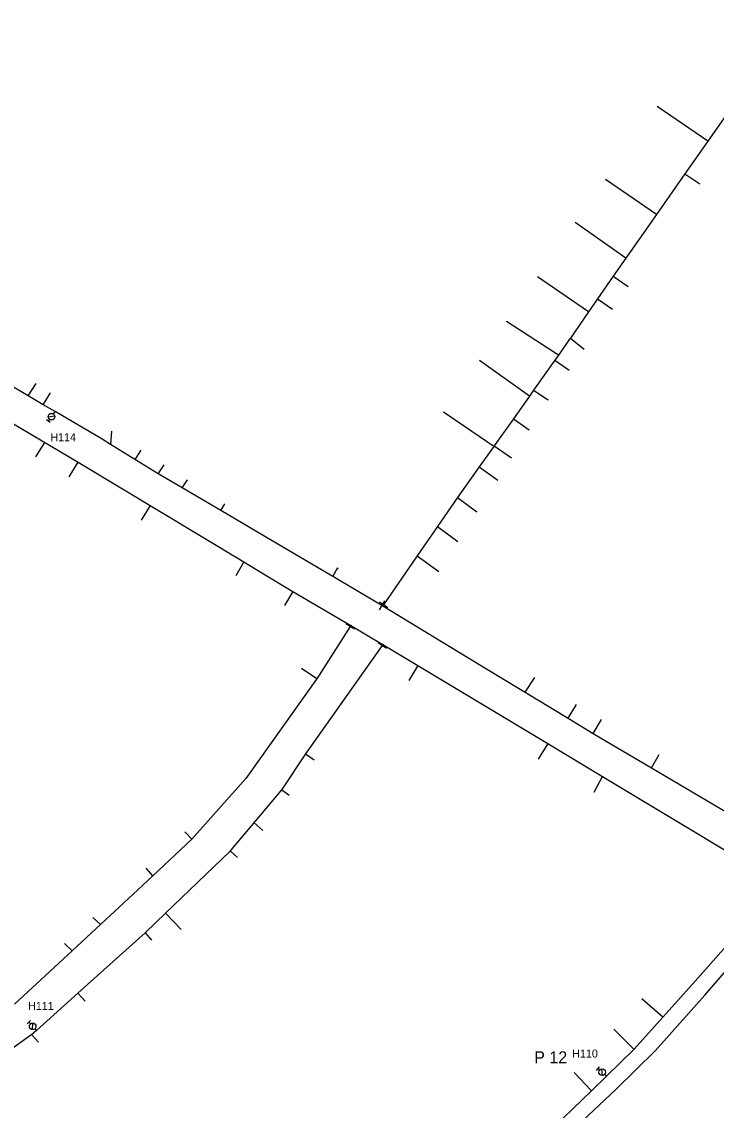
# Model space of a CAD drawing. Extents: x -548873 to -538270, y -1201997 to -1192514.
# Drawn here: x -544179.8 to -544006.3, y -1193175.5 to -1192903.5 of the extents above; entities that cross this region are included whole.
import ezdxf

# ---------------------------------------------------------------- set-up
doc = ezdxf.new("R2010")
doc.units = 0
for name, color, linetype in [('KN_HRAN_STÁTNÍ', 7, 'Continuous'), ('KN_PARC_Č', 7, 'Continuous'), ('KN_VKP_HRAN_SPORNÁ', 7, 'Continuous'), ('PK_PARC_Čv', 7, 'Continuous'), ('Vrstva 29', 7, 'Continuous')]:
    doc.layers.add(name, color=color, linetype=linetype)

# ---------------------------------------------------------------- blocks, each defined once
blk = doc.blocks.new('160')
at = {"layer": 'KN_HRAN_STÁTNÍ'}
blk.add_circle((0, 0), 0.0458, dxfattribs=at)
blk = doc.blocks.new('147')
at = {"layer": 'KN_HRAN_STÁTNÍ'}
blk.add_line((0, 1.27), (0, -1.27), dxfattribs=at)
blk = doc.blocks.new('133')
at = {"layer": 'KN_HRAN_STÁTNÍ'}
for p, q in [((0.28, 0), (0, 0)), ((0.54, 0.58), (1.7, -0.58)), ((1.94, 0), (2.52, 0)), ((2.52, 0.58), (2.52, -0.58))]:
    blk.add_line(p, q, dxfattribs=at)
blk.add_circle((1.11, 0), 0.825, dxfattribs=at)

msp = doc.modelspace()

# ---------------------------------------------------------------- linework, layer by layer
at = {"layer": 'KN_PARC_Č'}
for points in [[(-544008.387, -1192933.391), (-544021.058, -1192924.736)], [(-544021.221, -1192951.705), (-544033.938, -1192942.937)], [(-544014.091, -1192941.565), (-544010.359, -1192944.037)], [(-544028.888, -1192962.608), (-544041.542, -1192953.662)], [(-544038.189, -1192975.993), (-544050.926, -1192967.248)], [(-544032.028, -1192967.074), (-544028.307, -1192969.644)], [(-544035.944, -1192972.743), (-544032.204, -1192975.347)], [(-544045.731, -1192986.825), (-544058.699, -1192978.403)], [(-544042.741, -1192982.583), (-544039.264, -1192985.361)], [(-544052.942, -1192997.05), (-544065.489, -1192988.196)], [(-544046.636, -1192988.108), (-544043.031, -1192990.552)], [(-544178.257, -1192997.017), (-544176.267, -1192993.909)], [(-544174.516, -1192999.205), (-544172.625, -1192996.288)], [(-544051.933, -1192995.619), (-544048.311, -1192997.974)], [(-544061.89, -1193009.624), (-544074.426, -1193001.119)], [(-544056.979, -1193002.723), (-544053, -1193005.522)], [(-544157.602, -1193009.165), (-544157.322, -1193005.806)], [(-544174.129, -1193008.617), (-544176.401, -1193012.255)], [(-544151.525, -1193012.911), (-544149.983, -1193010.556)], [(-544061.78, -1193009.47), (-544057.485, -1193012.489)], [(-544165.804, -1193013.531), (-544168.08, -1193017.275)], [(-544145.737, -1193016.479), (-544144.251, -1193014.222)], [(-544065.508, -1193014.709), (-544060.898, -1193018.072)], [(-544139.736, -1193020.008), (-544138.398, -1193018.021)], [(-544147.754, -1193024.394), (-544150.019, -1193028.09)], [(-544130.135, -1193025.655), (-544129.12, -1193024.02)], [(-544070.961, -1193022.372), (-544066.089, -1193025.943)], [(-544075.98, -1193029.639), (-544070.833, -1193033.354)], [(-544081.061, -1193036.999), (-544075.641, -1193040.854)], [(-544124.358, -1193038.476), (-544126.372, -1193041.963)], [(-544102.075, -1193042.159), (-544100.864, -1193039.903)], [(-544101.026, -1193040.204), (-544100.67, -1193040.057)], [(-544112.09, -1193045.86), (-544114.147, -1193049.349)], [(-544106.12, -1193067.738), (-544109.913, -1193065.159)], [(-544080.84, -1193064.369), (-544083.103, -1193068.144)], [(-544054.015, -1193071.064), (-544051.579, -1193067.401)], [(-544043.296, -1193077.56), (-544041.178, -1193074.094)], [(-544037.046, -1193081.348), (-544034.977, -1193077.846)], [(-544048.396, -1193083.832), (-544050.746, -1193087.813)], [(-544108.927, -1193086.404), (-544106.729, -1193087.936)], [(-544022.497, -1193089.945), (-544020.577, -1193086.586)], [(-544034.732, -1193092.062), (-544036.91, -1193096.096)], [(-544114.895, -1193095.316), (-544112.994, -1193096.76)], [(-544137.317, -1193107.771), (-544139.114, -1193105.935)], [(-544121.82, -1193103.584), (-544119.612, -1193105.601)], [(-544127.781, -1193110.7), (-544125.959, -1193112.362)], [(-544147.085, -1193116.945), (-544148.783, -1193114.971)], [(-544160.187, -1193129.099), (-544162.061, -1193127.309)], [(-544143.938, -1193126.293), (-544139.971, -1193130.315)], [(-544149.001, -1193131.172), (-544147.424, -1193133.005)], [(-544167.251, -1193135.652), (-544169.156, -1193133.848)], [(-544165.873, -1193146.274), (-544164.001, -1193148.203)], [(-544019.644, -1193152.21), (-544024.849, -1193147.69)], [(-544177.353, -1193156.615), (-544175.664, -1193158.482)], [(-544026.856, -1193160.247), (-544031.866, -1193155.254)], [(-544037.454, -1193170.669), (-544041.79, -1193166.057)]]:
    msp.add_lwpolyline(points, dxfattribs=at)
at = {"layer": 'KN_VKP_HRAN_SPORNÁ'}
for points in [[(-543987.554, -1192903.537), (-543994.599, -1192913.633), (-544005.63, -1192929.441), (-544008.387, -1192933.391), (-544014.091, -1192941.565), (-544021.221, -1192951.705), (-544032.028, -1192967.074), (-544035.944, -1192972.743), (-544038.189, -1192975.993), (-544042.742, -1192982.584), (-544042.929, -1192982.851), (-544045.731, -1192986.825), (-544046.636, -1192988.108), (-544051.935, -1192995.621), (-544052.942, -1192997.05), (-544056.98, -1193002.725), (-544061.78, -1193009.47), (-544061.89, -1193009.624), (-544065.509, -1193014.71), (-544070.961, -1193022.372), (-544075.98, -1193029.639), (-544081.061, -1193036.998), (-544089.427, -1193049.251)], [(-544089.855, -1193049.347), (-544102.076, -1193042.159), (-544117.278, -1193033.217), (-544130.134, -1193025.656), (-544139.736, -1193020.008), (-544145.75, -1193016.471), (-544157.635, -1193009.145), (-544159.757, -1193007.837), (-544171.53, -1193000.951), (-544174.516, -1192999.205), (-544178.257, -1192997.017), (-544188.523, -1192991.013), (-544190.431, -1192989.897), (-544197.927, -1192985.759), (-544213.044, -1192979.259), (-544220.592, -1192976.683), (-544221.484, -1192976.379), (-544229.477, -1192973.45), (-544246.01, -1192968.29), (-544260.273, -1192963.444), (-544278.402, -1192957.285)], [(-544224.048, -1192984.419), (-544217.124, -1192986.365), (-544208.14, -1192988.89), (-544206.053, -1192990.229), (-544204.619, -1192991.15), (-544186.94, -1193001.055), (-544165.773, -1193013.549), (-544124.358, -1193038.476), (-544119.842, -1193041.194), (-544112.061, -1193045.877), (-544097.58, -1193054.366)], [(-544089.596, -1193049.499), (-544089.855, -1193049.347)], [(-544089.427, -1193049.251), (-544089.596, -1193049.499)], [(-544089.596, -1193049.499), (-544063.674, -1193065.21), (-544043.296, -1193077.56), (-544037.046, -1193081.349), (-544022.496, -1193089.945), (-544005.384, -1193100.056), (-543984.659, -1193112.301), (-543984.54, -1193112.42)], [(-544097.58, -1193054.366), (-544097.741, -1193054.619)], [(-544097.58, -1193054.366), (-544097.585, -1193054.363), (-544096.173, -1193055.203), (-544092.429, -1193057.431), (-544089.577, -1193059.128)], [(-544097.741, -1193054.619), (-544104.325, -1193064.926), (-544106.12, -1193067.737), (-544106.148, -1193067.781), (-544117.674, -1193083.955), (-544123.817, -1193092.575), (-544137.317, -1193107.771), (-544137.34, -1193107.797), (-544147.086, -1193116.946), (-544150.869, -1193120.455), (-544160.188, -1193129.1), (-544167.251, -1193135.652), (-544181.641, -1193149.001)], [(-544089.762, -1193059.399), (-544108.927, -1193086.404), (-544108.935, -1193086.416), (-544114.892, -1193095.313), (-544127.781, -1193110.7), (-544127.875, -1193110.813), (-544143.938, -1193126.293), (-544148.995, -1193131.167), (-544149.001, -1193131.172), (-544165.873, -1193146.274), (-544176.167, -1193155.556), (-544177.3, -1193156.577), (-544189.492, -1193165.255), (-544207.544, -1193177.774), (-544220.163, -1193186.006), (-544226.481, -1193190.224), (-544238.839, -1193198.475)], [(-544089.762, -1193059.399), (-544089.577, -1193059.128)], [(-544089.577, -1193059.128), (-544080.838, -1193064.37), (-544048.376, -1193083.844), (-544034.709, -1193092.076), (-544000.466, -1193112.661), (-543990.613, -1193118.584), (-543990.374, -1193118.783)], [(-544345.745, -1193444.61), (-544343.348, -1193443.882), (-544324.303, -1193438.096), (-544308.937, -1193423.077), (-544301.353, -1193415.664), (-544300.262, -1193414.734), (-544299.949, -1193414.468), (-544256.263, -1193375.958), (-544244.022, -1193365.058), (-544211.153, -1193335.791), (-544164.9, -1193294.332), (-544162.049, -1193291.777), (-544118.276, -1193252.536), (-544093.677, -1193229.114), (-544073.439, -1193209.843), (-544031.304, -1193170.221), (-544021.493, -1193160.525), (-544009.164, -1193146.705), (-543992.901, -1193127.997), (-543982.272, -1193115.771), (-543979.5, -1193112.583), (-543979.069, -1193112.02)], [(-543990.185, -1193119.36), (-543990.569, -1193119.789), (-544001.851, -1193132.369), (-544011.576, -1193143.213), (-544026.824, -1193160.216), (-544033.682, -1193166.96), (-544037.468, -1193170.683), (-544049.173, -1193181.955), (-544056.195, -1193188.717), (-544060.141, -1193192.517), (-544060.171, -1193192.546), (-544068.739, -1193200.6), (-544078.191, -1193209.486), (-544093.98, -1193224.329), (-544102.083, -1193231.947), (-544119.64, -1193248.654), (-544129.282, -1193258.095), (-544143.756, -1193271.606), (-544151.187, -1193278.063), (-544166.907, -1193291.698)]]:
    msp.add_lwpolyline(points, dxfattribs=at)
at = {"layer": 'PK_PARC_Čv'}
for points in [[(-544171.531, -1193000.951), (-544171.773, -1193001.285)], [(-544176.166, -1193155.555), (-544176.361, -1193155.345)], [(-544033.682, -1193166.96), (-544033.936, -1193166.736)]]:
    msp.add_lwpolyline(points, dxfattribs=at)

# ---------------------------------------------------------------- block references
for p, xscale, yscale, rotation in [((-544171.773, -1193001.285), 1.000000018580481, 1.000000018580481, -125.00000023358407), ((-544176.361, -1193155.345), 1.00000000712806, 1.00000000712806, 133.00000056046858), ((-544033.936, -1193166.736), 1.0000000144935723, 1.0000000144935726, 139.00000089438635)]:
    msp.add_blockref('133', p, dxfattribs=dict(at, xscale=xscale, yscale=yscale, rotation=rotation))
at = {"layer": 'Vrstva 29'}
for name, p, xscale, yscale, rotation in [('147', (-544089.855, -1193049.347), 0.9999999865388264, 0.9999999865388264, -30.00000044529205), ('147', (-544089.427, -1193049.251), 0.9999999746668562, 0.999999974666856, -124.00000045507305), ('160', (-544089.596, -1193049.499), 0.9999999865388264, 0.9999999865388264, 149.99999955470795), ('147', (-544097.741, -1193054.619), 0.9999999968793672, 0.9999999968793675, -122.00000027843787), ('160', (-544097.58, -1193054.366), 1.0000000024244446, 1.0000000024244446, -75.99999967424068), ('147', (-544089.762, -1193059.399), 0.9999999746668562, 0.999999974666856, -124.00000045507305), ('160', (-544089.577, -1193059.128), 0.9999999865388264, 0.9999999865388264, -120.00000044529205)]:
    msp.add_blockref(name, p, dxfattribs=dict(at, xscale=xscale, yscale=yscale, rotation=rotation))

# ---------------------------------------------------------------- texts
at = {"layer": 'PK_PARC_Čv'}
for s, height, p in [('H114', 2, (-544172.703, -1193008.335)), ('H111', 2, (-544178.261, -1193150.415)), ('H110', 2, (-544042.266, -1193162.326)), ('P 12', 3, (-544051.776, -1193163.766))]:
    msp.add_text(s, height=height, dxfattribs=at).set_placement(p)

doc.saveas('drawing.dxf')
